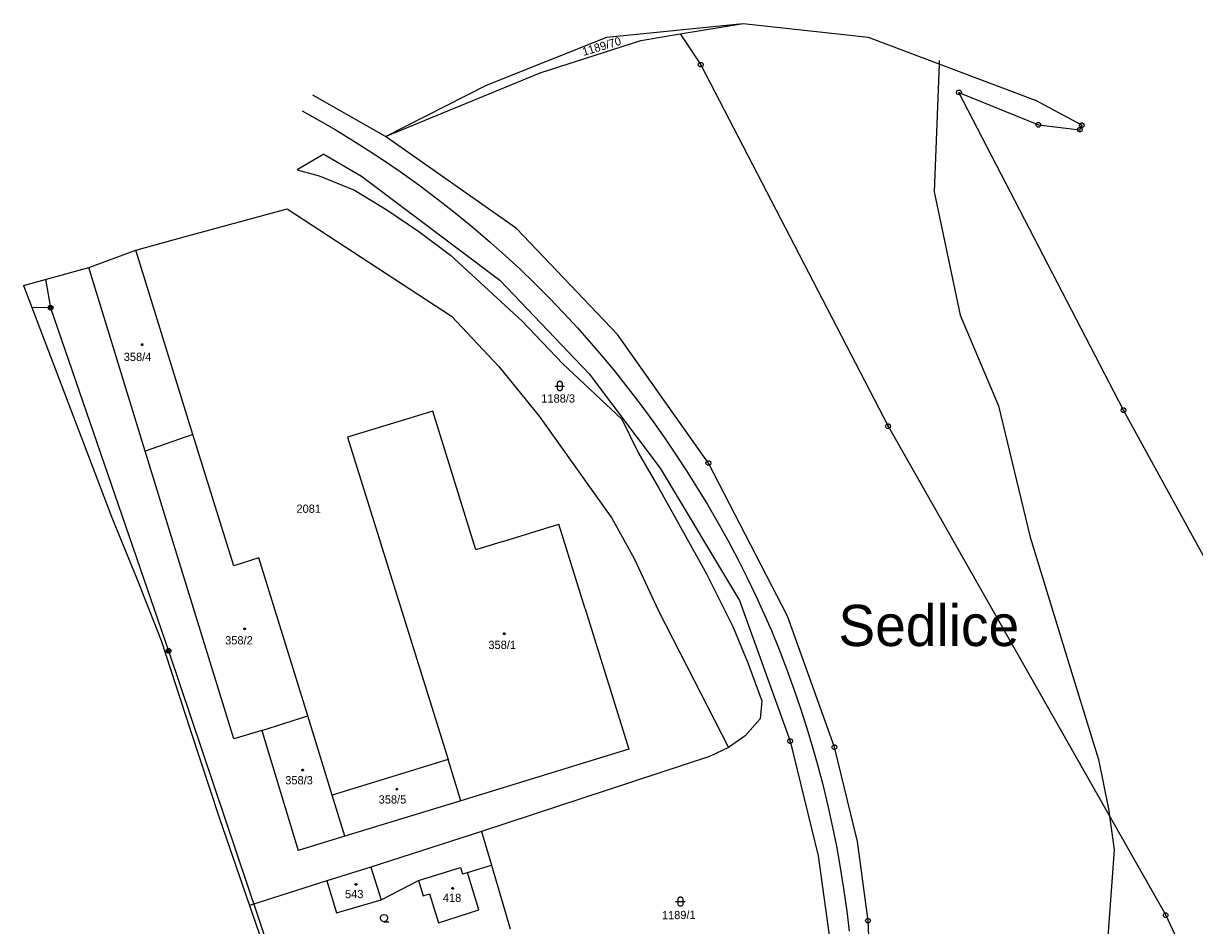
# Model space of a CAD drawing. Extents: x -789470 to -786707, y -1118640 to -1114455.
# Drawn here: x -787871.3 to -787629.8, y -1116508.7 to -1116322.8 of the extents above; entities that cross this region are included whole.
import ezdxf

# ---------------------------------------------------------------- set-up
doc = ezdxf.new("R2010")
doc.units = 0
for name, color, linetype in [('1', 7, 'Continuous'), ('11', 7, 'Continuous'), ('12', 7, 'Continuous'), ('2', 7, 'Continuous'), ('3', 7, 'Continuous'), ('4', 7, 'Continuous'), ('5', 7, 'Continuous'), ('6', 7, 'Continuous'), ('7', 7, 'Continuous'), ('8', 7, 'Continuous')]:
    doc.layers.add(name, color=color, linetype=linetype)

msp = doc.modelspace()

# ---------------------------------------------------------------- linework, layer by layer
at = {"layer": '1'}
for p, q in [((-787751, -1116325.62), (-787722.89, -1116322.78)), ((-787735.88, -1116324.94), (-787722.89, -1116322.78)), ((-787722.89, -1116322.78), (-787697.16, -1116325.6)), ((-787775.84, -1116335.51), (-787751, -1116325.62)), ((-787744.01, -1116326.3), (-787735.88, -1116324.94)), ((-787735.88, -1116324.94), (-787731.65, -1116331.28)), ((-787697.16, -1116325.6), (-787662.68, -1116338.61)), ((-787764.77, -1116332.97), (-787744.01, -1116326.3)), ((-787796.66, -1116346.09), (-787764.77, -1116332.97)), ((-787731.65, -1116331.28), (-787693.03, -1116405.8)), ((-787796.66, -1116346.09), (-787811.61, -1116337.55)), ((-787796.66, -1116346.09), (-787775.84, -1116335.51)), ((-787644.49, -1116402.5), (-787678.42, -1116337)), ((-787678.42, -1116337), (-787662.05, -1116343.67)), ((-787653.08, -1116343.75), (-787662.68, -1116338.61)), ((-787662.05, -1116343.67), (-787653.49, -1116344.69)), ((-787653.49, -1116344.69), (-787653.08, -1116343.75)), ((-787769.63, -1116365.02), (-787796.66, -1116346.09)), ((-787809.33, -1116349.7), (-787814.88, -1116352.94)), ((-787809.33, -1116349.7), (-787801.57, -1116354.26)), ((-787814.88, -1116352.94), (-787810.31, -1116354.2)), ((-787810.31, -1116354.2), (-787803.06, -1116357.15)), ((-787801.57, -1116354.26), (-787773.08, -1116375.71)), ((-787803.06, -1116357.15), (-787796.38, -1116361.2)), ((-787838.93, -1116367), (-787816.95, -1116360.96)), ((-787816.95, -1116360.96), (-787783.07, -1116383.09)), ((-787796.38, -1116361.2), (-787789.77, -1116365.68)), ((-787789.77, -1116365.68), (-787783.23, -1116370.57)), ((-787748.85, -1116386.9), (-787769.63, -1116365.02)), ((-787848.15, -1116369.53), (-787838.93, -1116367)), ((-787857.79, -1116373.06), (-787848.15, -1116369.53)), ((-787836.34, -1116407.53), (-787848.15, -1116369.53)), ((-787783.23, -1116370.57), (-787768.48, -1116384.12)), ((-787871.3, -1116376.78), (-787857.79, -1116373.06)), ((-787846.17, -1116410.91), (-787857.79, -1116373.06)), ((-787773.08, -1116375.71), (-787754.69, -1116394.98)), ((-787871.3, -1116376.78), (-787853.08, -1116424.6)), ((-787783.07, -1116383.09), (-787773.29, -1116393.47)), ((-787768.48, -1116384.12), (-787760.07, -1116392.95)), ((-787730.07, -1116413.4), (-787748.85, -1116386.9)), ((-787760.07, -1116392.95), (-787747.91, -1116404.33)), ((-787773.29, -1116393.47), (-787764.99, -1116403.74)), ((-787754.69, -1116394.98), (-787740.05, -1116414.46)), ((-787786.89, -1116402.68), (-787804.46, -1116408.04)), ((-787778, -1116431.3), (-787786.89, -1116402.68)), ((-787607.93, -1116469.17), (-787644.49, -1116402.5)), ((-787764.99, -1116403.74), (-787750.02, -1116424.78)), ((-787747.91, -1116404.33), (-787744.48, -1116411.34)), ((-787836.34, -1116407.53), (-787846.17, -1116410.91)), ((-787829.71, -1116428.88), (-787836.34, -1116407.53)), ((-787693.03, -1116405.8), (-787635.8, -1116506.59)), ((-787804.46, -1116408.04), (-787783.74, -1116474.49)), ((-787839.65, -1116432.16), (-787846.17, -1116410.91)), ((-787744.48, -1116411.34), (-787740.3, -1116418.54)), ((-787740.05, -1116414.46), (-787723.7, -1116441.75)), ((-787713.77, -1116444.97), (-787730.07, -1116413.4)), ((-787740.3, -1116418.54), (-787730.48, -1116436.2)), ((-787853.08, -1116424.6), (-787847.88, -1116437.41)), ((-787772.45, -1116429.58), (-787760.88, -1116425.98)), ((-787755.47, -1116443.43), (-787760.88, -1116425.98)), ((-787750.02, -1116424.78), (-787745.39, -1116433.08)), ((-787827.94, -1116434.57), (-787829.71, -1116428.88)), ((-787772.45, -1116429.58), (-787778, -1116431.3)), ((-787827.95, -1116470.26), (-787839.65, -1116432.16)), ((-787822.78, -1116432.96), (-787827.94, -1116434.57)), ((-787812.66, -1116465.52), (-787822.78, -1116432.96)), ((-787745.39, -1116433.08), (-787740.36, -1116443.85)), ((-787730.48, -1116436.2), (-787725.06, -1116447.09)), ((-787847.88, -1116437.41), (-787842.91, -1116449.97)), ((-787755.47, -1116443.43), (-787746.51, -1116472.35)), ((-787740.36, -1116443.85), (-787725.95, -1116472.01)), ((-787723.7, -1116441.75), (-787713.22, -1116470.7)), ((-787704.1, -1116471.95), (-787713.77, -1116444.97)), ((-787725.06, -1116447.09), (-787721.94, -1116454.54)), ((-787842.91, -1116449.97), (-787836.94, -1116468.33)), ((-787721.94, -1116454.54), (-787719.06, -1116462.43)), ((-787719.06, -1116462.43), (-787719.42, -1116466.14)), ((-787822.15, -1116468.48), (-787812.66, -1116465.52)), ((-787807.65, -1116481.83), (-787812.66, -1116465.52)), ((-787719.42, -1116466.14), (-787722.51, -1116469.58)), ((-787836.94, -1116468.33), (-787830.95, -1116486.46)), ((-787822.15, -1116468.48), (-787827.95, -1116470.26)), ((-787822.15, -1116468.48), (-787814.66, -1116493.27)), ((-787722.51, -1116469.58), (-787725.95, -1116472.01)), ((-787746.51, -1116472.35), (-787781.13, -1116482.98)), ((-787725.95, -1116472.01), (-787729.82, -1116473.87)), ((-787713.22, -1116470.7), (-787707.44, -1116494.38)), ((-787699.35, -1116491.37), (-787704.1, -1116471.95)), ((-787783.74, -1116474.49), (-787807.65, -1116481.83)), ((-787781.13, -1116482.98), (-787783.74, -1116474.49)), ((-787729.82, -1116473.87), (-787776.83, -1116489.36)), ((-787805.05, -1116490.32), (-787807.65, -1116481.83)), ((-787781.13, -1116482.98), (-787805.05, -1116490.32)), ((-787830.95, -1116486.46), (-787824.68, -1116504.6)), ((-787776.83, -1116489.36), (-787799.7, -1116496.65)), ((-787776.83, -1116489.36), (-787774.8, -1116496.28)), ((-787805.05, -1116490.32), (-787814.66, -1116493.27)), ((-787697.17, -1116507.73), (-787699.35, -1116491.37)), ((-787707.44, -1116494.38), (-787704.74, -1116513.73)), ((-787799.7, -1116496.65), (-787808.76, -1116499.53)), ((-787799.7, -1116496.65), (-787797.55, -1116503.4)), ((-787779.76, -1116497.81), (-787774.8, -1116496.28)), ((-787774.8, -1116496.28), (-787770.94, -1116509.39)), ((-787808.76, -1116499.53), (-787824.68, -1116504.6)), ((-787808.76, -1116499.53), (-787806.78, -1116506.12)), ((-787797.55, -1116503.4), (-787789.88, -1116499.46)), ((-787789.88, -1116499.46), (-787788.87, -1116502.58)), ((-787777.4, -1116505.49), (-787779.76, -1116497.81)), ((-787806.78, -1116506.12), (-787797.55, -1116503.4)), ((-787788.87, -1116502.58), (-787787.57, -1116502.18)), ((-787787.57, -1116502.18), (-787785.72, -1116508.13)), ((-787824.68, -1116504.6), (-787819.38, -1116520)), ((-787785.72, -1116508.13), (-787777.4, -1116505.49)), ((-787635.8, -1116506.59), (-787568.9, -1116647.88)), ((-787695.53, -1116543.16), (-787697.17, -1116507.73))]:
    msp.add_line(p, q, dxfattribs=at)
at = {"layer": '11'}
msp.add_lwpolyline([(-787682.47, -1116330.41), (-787682.5, -1116331.13), (-787683.51, -1116357.47), (-787678.19, -1116382.89), (-787670.29, -1116401.57), (-787663.71, -1116428.69), (-787655.44, -1116455.83), (-787649.65, -1116474.49), (-787647.6, -1116484.65), (-787646.4, -1116493.12), (-787648.27, -1116518.48), (-787648.86, -1116540.46), (-787650.19, -1116548.91), (-787652.39, -1116560.73), (-787656.3, -1116574.23), (-787661.06, -1116587.72), (-787663.2, -1116591.08), (-787677.78, -1116616.32), (-787688.91, -1116633.13), (-787692.34, -1116638.18), (-787695.11, -1116645.4), (-787696.22, -1116648.29), (-787697.58, -1116660.12)], dxfattribs=at)
at = {"layer": '12'}
for p, q in [((-787857.79, -1116373.06), (-787848.15, -1116369.53)), ((-787836.34, -1116407.53), (-787848.15, -1116369.53)), ((-787846.17, -1116410.91), (-787857.79, -1116373.06)), ((-787786.89, -1116402.68), (-787804.46, -1116408.04)), ((-787778, -1116431.3), (-787786.89, -1116402.68)), ((-787836.34, -1116407.53), (-787846.17, -1116410.91)), ((-787836.34, -1116407.53), (-787846.17, -1116410.91)), ((-787829.71, -1116428.88), (-787836.34, -1116407.53)), ((-787804.46, -1116408.04), (-787783.74, -1116474.49)), ((-787839.65, -1116432.16), (-787846.17, -1116410.91)), ((-787772.45, -1116429.58), (-787760.88, -1116425.98)), ((-787755.47, -1116443.43), (-787760.88, -1116425.98)), ((-787827.94, -1116434.57), (-787829.71, -1116428.88)), ((-787772.45, -1116429.58), (-787778, -1116431.3)), ((-787827.95, -1116470.26), (-787839.65, -1116432.16)), ((-787822.78, -1116432.96), (-787827.94, -1116434.57)), ((-787812.66, -1116465.52), (-787822.78, -1116432.96)), ((-787755.47, -1116443.43), (-787746.51, -1116472.35)), ((-787822.15, -1116468.48), (-787812.66, -1116465.52)), ((-787822.15, -1116468.48), (-787812.66, -1116465.52)), ((-787807.65, -1116481.83), (-787812.66, -1116465.52)), ((-787822.15, -1116468.48), (-787827.95, -1116470.26)), ((-787822.15, -1116468.48), (-787814.66, -1116493.27)), ((-787746.51, -1116472.35), (-787781.13, -1116482.98)), ((-787783.74, -1116474.49), (-787807.65, -1116481.83)), ((-787781.13, -1116482.98), (-787783.74, -1116474.49)), ((-787781.13, -1116482.98), (-787783.74, -1116474.49)), ((-787805.05, -1116490.32), (-787807.65, -1116481.83)), ((-787805.05, -1116490.32), (-787807.65, -1116481.83)), ((-787781.13, -1116482.98), (-787805.05, -1116490.32)), ((-787805.05, -1116490.32), (-787814.66, -1116493.27)), ((-787799.7, -1116496.65), (-787808.76, -1116499.53)), ((-787799.7, -1116496.65), (-787797.55, -1116503.4)), ((-787789.88, -1116499.46), (-787781.17, -1116496.76)), ((-787781.17, -1116496.76), (-787780.77, -1116498.06)), ((-787808.76, -1116499.53), (-787806.78, -1116506.12)), ((-787789.88, -1116499.46), (-787788.87, -1116502.58)), ((-787780.77, -1116498.06), (-787779.76, -1116497.81)), ((-787777.4, -1116505.49), (-787779.76, -1116497.81)), ((-787806.78, -1116506.12), (-787797.55, -1116503.4)), ((-787788.87, -1116502.58), (-787787.57, -1116502.18)), ((-787787.57, -1116502.18), (-787785.72, -1116508.13)), ((-787785.72, -1116508.13), (-787777.4, -1116505.49))]:
    msp.add_line(p, q, dxfattribs=at)
at = {"layer": '3'}
for points in [[(-787761.72, -1116397.51), (-787760.45, -1116397.51), (-787759.72, -1116397.51)], [(-787736.84, -1116503.78), (-787735.57, -1116503.78), (-787734.84, -1116503.78)], [(-787796.95, -1116507.92), (-787797.33, -1116507.82), (-787797.6, -1116507.55), (-787797.7, -1116507.18), (-787797.6, -1116506.81), (-787797.33, -1116506.54), (-787796.96, -1116506.44), (-787796.59, -1116506.54), (-787796.32, -1116506.81), (-787796.22, -1116507.19), (-787796.32, -1116507.57), (-787796.59, -1116507.84), (-787796.97, -1116507.94), (-787795.97, -1116507.94)]]:
    msp.add_lwpolyline(points, dxfattribs=at)
for points in [[(-787761.22, -1116397.01), (-787761.12, -1116396.72), (-787760.87, -1116396.54), (-787760.56, -1116396.54), (-787760.31, -1116396.72), (-787760.21, -1116397.01), (-787760.21, -1116398.01), (-787760.31, -1116398.3), (-787760.56, -1116398.48), (-787760.87, -1116398.48), (-787761.12, -1116398.3), (-787761.22, -1116398.01)], [(-787736.34, -1116503.28), (-787736.24, -1116502.99), (-787735.99, -1116502.81), (-787735.68, -1116502.81), (-787735.43, -1116502.99), (-787735.33, -1116503.28), (-787735.33, -1116504.28), (-787735.43, -1116504.57), (-787735.68, -1116504.75), (-787735.99, -1116504.75), (-787736.24, -1116504.57), (-787736.34, -1116504.28)]]:
    msp.add_lwpolyline(points, close=True, dxfattribs=at)
at = {"layer": '4'}
for p, q in [((-787789.88, -1116499.46), (-787781.17, -1116496.76)), ((-787781.17, -1116496.76), (-787780.77, -1116498.06)), ((-787780.77, -1116498.06), (-787779.76, -1116497.81))]:
    msp.add_line(p, q, dxfattribs=at)
at = {"layer": '5'}
for points in [[(-787846.8, -1116388.83), (-787846.7, -1116388.85), (-787846.65, -1116388.94), (-787846.63, -1116389), (-787846.65, -1116389.09), (-787846.73, -1116389.16), (-787846.8, -1116389.17), (-787846.89, -1116389.14), (-787846.95, -1116389.08), (-787846.97, -1116389), (-787846.95, -1116388.91), (-787846.87, -1116388.84)], [(-787825.69, -1116447.4), (-787825.59, -1116447.42), (-787825.54, -1116447.51), (-787825.52, -1116447.57), (-787825.54, -1116447.66), (-787825.62, -1116447.73), (-787825.69, -1116447.74), (-787825.78, -1116447.71), (-787825.84, -1116447.65), (-787825.86, -1116447.57), (-787825.84, -1116447.48), (-787825.76, -1116447.41)], [(-787772.15, -1116448.4), (-787772.05, -1116448.42), (-787772, -1116448.51), (-787771.98, -1116448.57), (-787772, -1116448.66), (-787772.08, -1116448.73), (-787772.15, -1116448.74), (-787772.24, -1116448.71), (-787772.3, -1116448.65), (-787772.32, -1116448.57), (-787772.3, -1116448.48), (-787772.22, -1116448.41)], [(-787813.72, -1116476.5), (-787813.62, -1116476.52), (-787813.57, -1116476.61), (-787813.55, -1116476.67), (-787813.57, -1116476.76), (-787813.65, -1116476.83), (-787813.72, -1116476.84), (-787813.81, -1116476.81), (-787813.87, -1116476.75), (-787813.89, -1116476.67), (-787813.87, -1116476.58), (-787813.79, -1116476.51)], [(-787794.33, -1116480.44), (-787794.23, -1116480.46), (-787794.18, -1116480.55), (-787794.16, -1116480.61), (-787794.18, -1116480.7), (-787794.26, -1116480.77), (-787794.33, -1116480.78), (-787794.42, -1116480.75), (-787794.48, -1116480.69), (-787794.5, -1116480.61), (-787794.48, -1116480.52), (-787794.4, -1116480.45)], [(-787802.72, -1116500.06), (-787802.62, -1116500.08), (-787802.57, -1116500.17), (-787802.55, -1116500.23), (-787802.57, -1116500.32), (-787802.65, -1116500.39), (-787802.72, -1116500.4), (-787802.81, -1116500.37), (-787802.87, -1116500.31), (-787802.89, -1116500.23), (-787802.87, -1116500.14), (-787802.79, -1116500.07)], [(-787782.8, -1116500.87), (-787782.7, -1116500.89), (-787782.65, -1116500.98), (-787782.63, -1116501.04), (-787782.65, -1116501.13), (-787782.73, -1116501.2), (-787782.8, -1116501.21), (-787782.89, -1116501.18), (-787782.95, -1116501.12), (-787782.97, -1116501.04), (-787782.95, -1116500.95), (-787782.87, -1116500.88)]]:
    msp.add_lwpolyline(points, close=True, dxfattribs=at)
at = {"layer": '6'}
for p, q in [((-787866.72, -1116375.52), (-787865.71, -1116381.37)), ((-787865.71, -1116381.37), (-787869.58, -1116381.31)), ((-787865.71, -1116381.37), (-787841.37, -1116452.11)), ((-787841.37, -1116452.11), (-787814.56, -1116531.75))]:
    msp.add_line(p, q, dxfattribs=at)
for points in [[(-787813.81, -1116340.77), (-787810.52, -1116342.62), (-787807.04, -1116344.65), (-787803.61, -1116346.75), (-787800.21, -1116348.91), (-787797.06, -1116350.99), (-787793.65, -1116353.32), (-787789.79, -1116356.08), (-787785.99, -1116358.93), (-787782.26, -1116361.85), (-787778.59, -1116364.85), (-787774.98, -1116367.93), (-787771.89, -1116370.68)], [(-787771.89, -1116370.68), (-787769.03, -1116373.32), (-787765.95, -1116376.29), (-787762.93, -1116379.31), (-787759.96, -1116382.4), (-787757.06, -1116385.54), (-787754.22, -1116388.74), (-787751.69, -1116391.7), (-787749.22, -1116394.68), (-787746.59, -1116398), (-787744.02, -1116401.36), (-787741.51, -1116404.78), (-787739.07, -1116408.24), (-787736.7, -1116411.75), (-787734.6, -1116415)], [(-787865.86, -1116380.89), (-787865.55, -1116380.89), (-787865.3, -1116381.07), (-787865.2, -1116381.36), (-787865.3, -1116381.65), (-787865.55, -1116381.83), (-787865.86, -1116381.83), (-787866.11, -1116381.65), (-787866.21, -1116381.36), (-787866.11, -1116381.07), (-787865.86, -1116380.89), (-787865.83, -1116380.93), (-787865.59, -1116380.93), (-787865.43, -1116381.01), (-787865.99, -1116381.01), (-787866.07, -1116381.09), (-787865.35, -1116381.09), (-787865.35, -1116381.17), (-787866.07, -1116381.17), (-787866.11, -1116381.25), (-787865.31, -1116381.25), (-787865.27, -1116381.33), (-787866.15, -1116381.33), (-787866.15, -1116381.41), (-787865.27, -1116381.41), (-787865.3, -1116381.49), (-787866.11, -1116381.49), (-787866.1, -1116381.57), (-787865.29, -1116381.57), (-787865.34, -1116381.65), (-787866.06, -1116381.65), (-787865.98, -1116381.73), (-787865.42, -1116381.73), (-787865.53, -1116381.81), (-787865.87, -1116381.81)], [(-787734.6, -1116415), (-787732.52, -1116418.26), (-787730.27, -1116421.92), (-787728.11, -1116425.63), (-787726.02, -1116429.39), (-787724.01, -1116433.19), (-787722.07, -1116437.02), (-787720.22, -1116440.9), (-787718.62, -1116444.42), (-787717.09, -1116447.93), (-787715.48, -1116451.85), (-787713.96, -1116455.79), (-787712.51, -1116459.77), (-787711.14, -1116463.77), (-787709.85, -1116467.8), (-787708.76, -1116471.47)], [(-787841.52, -1116451.63), (-787841.21, -1116451.63), (-787840.96, -1116451.81), (-787840.86, -1116452.1), (-787840.96, -1116452.39), (-787841.21, -1116452.57), (-787841.52, -1116452.57), (-787841.77, -1116452.39), (-787841.87, -1116452.1), (-787841.77, -1116451.81), (-787841.52, -1116451.63), (-787841.49, -1116451.67), (-787841.25, -1116451.67), (-787841.09, -1116451.75), (-787841.65, -1116451.75), (-787841.73, -1116451.83), (-787841.01, -1116451.83), (-787841.01, -1116451.91), (-787841.73, -1116451.91), (-787841.77, -1116451.99), (-787840.97, -1116451.99), (-787840.93, -1116452.07), (-787841.81, -1116452.07), (-787841.81, -1116452.15), (-787840.93, -1116452.15), (-787840.96, -1116452.23), (-787841.77, -1116452.23), (-787841.76, -1116452.31), (-787840.95, -1116452.31), (-787841, -1116452.39), (-787841.72, -1116452.39), (-787841.64, -1116452.47), (-787841.08, -1116452.47), (-787841.19, -1116452.55), (-787841.53, -1116452.55)], [(-787708.76, -1116471.47), (-787707.66, -1116475.3), (-787706.5, -1116479.65), (-787705.44, -1116484.02), (-787704.47, -1116488.41), (-787703.69, -1116492.32), (-787702.95, -1116496.37), (-787702.2, -1116501.07), (-787701.55, -1116505.78), (-787701.08, -1116509.87)]]:
    msp.add_lwpolyline(points, dxfattribs=at)
at = {"layer": '8'}
for p, q in [((-787731.77, -1116331.28), (-787731.53, -1116331.28)), ((-787678.54, -1116337), (-787678.3, -1116337)), ((-787662.17, -1116343.67), (-787661.93, -1116343.67)), ((-787653.61, -1116344.69), (-787653.37, -1116344.69)), ((-787653.2, -1116343.75), (-787652.96, -1116343.75)), ((-787644.61, -1116402.5), (-787644.37, -1116402.5)), ((-787693.15, -1116405.8), (-787692.91, -1116405.8)), ((-787730.19, -1116413.4), (-787729.95, -1116413.4)), ((-787713.34, -1116470.7), (-787713.1, -1116470.7)), ((-787704.22, -1116471.95), (-787703.98, -1116471.95)), ((-787635.92, -1116506.59), (-787635.68, -1116506.59)), ((-787697.29, -1116507.73), (-787697.05, -1116507.73))]:
    msp.add_line(p, q, dxfattribs=at)
for points in [[(-787731.5, -1116330.8), (-787731.25, -1116330.98), (-787731.15, -1116331.27), (-787731.25, -1116331.56), (-787731.5, -1116331.74), (-787731.81, -1116331.74), (-787732.06, -1116331.56), (-787732.16, -1116331.27), (-787732.06, -1116330.98), (-787731.81, -1116330.8)], [(-787678.27, -1116336.52), (-787678.02, -1116336.7), (-787677.92, -1116336.99), (-787678.02, -1116337.28), (-787678.27, -1116337.46), (-787678.58, -1116337.46), (-787678.83, -1116337.28), (-787678.93, -1116336.99), (-787678.83, -1116336.7), (-787678.58, -1116336.52)], [(-787661.9, -1116343.19), (-787661.65, -1116343.37), (-787661.55, -1116343.66), (-787661.65, -1116343.95), (-787661.9, -1116344.13), (-787662.21, -1116344.13), (-787662.46, -1116343.95), (-787662.56, -1116343.66), (-787662.46, -1116343.37), (-787662.21, -1116343.19)], [(-787653.34, -1116344.21), (-787653.09, -1116344.39), (-787652.99, -1116344.68), (-787653.09, -1116344.97), (-787653.34, -1116345.15), (-787653.65, -1116345.15), (-787653.9, -1116344.97), (-787654, -1116344.68), (-787653.9, -1116344.39), (-787653.65, -1116344.21)], [(-787652.93, -1116343.27), (-787652.68, -1116343.45), (-787652.58, -1116343.74), (-787652.68, -1116344.03), (-787652.93, -1116344.21), (-787653.24, -1116344.21), (-787653.49, -1116344.03), (-787653.59, -1116343.74), (-787653.49, -1116343.45), (-787653.24, -1116343.27)], [(-787644.34, -1116402.02), (-787644.09, -1116402.2), (-787643.99, -1116402.49), (-787644.09, -1116402.78), (-787644.34, -1116402.96), (-787644.65, -1116402.96), (-787644.9, -1116402.78), (-787645, -1116402.49), (-787644.9, -1116402.2), (-787644.65, -1116402.02)], [(-787692.88, -1116405.32), (-787692.63, -1116405.5), (-787692.53, -1116405.79), (-787692.63, -1116406.08), (-787692.88, -1116406.26), (-787693.19, -1116406.26), (-787693.44, -1116406.08), (-787693.54, -1116405.79), (-787693.44, -1116405.5), (-787693.19, -1116405.32)], [(-787729.92, -1116412.92), (-787729.67, -1116413.1), (-787729.57, -1116413.39), (-787729.67, -1116413.68), (-787729.92, -1116413.86), (-787730.23, -1116413.86), (-787730.48, -1116413.68), (-787730.58, -1116413.39), (-787730.48, -1116413.1), (-787730.23, -1116412.92)], [(-787713.07, -1116470.22), (-787712.82, -1116470.4), (-787712.72, -1116470.69), (-787712.82, -1116470.98), (-787713.07, -1116471.16), (-787713.38, -1116471.16), (-787713.63, -1116470.98), (-787713.73, -1116470.69), (-787713.63, -1116470.4), (-787713.38, -1116470.22)], [(-787703.95, -1116471.47), (-787703.7, -1116471.65), (-787703.6, -1116471.94), (-787703.7, -1116472.23), (-787703.95, -1116472.41), (-787704.26, -1116472.41), (-787704.51, -1116472.23), (-787704.61, -1116471.94), (-787704.51, -1116471.65), (-787704.26, -1116471.47)], [(-787635.65, -1116506.11), (-787635.4, -1116506.29), (-787635.3, -1116506.58), (-787635.4, -1116506.87), (-787635.65, -1116507.05), (-787635.96, -1116507.05), (-787636.21, -1116506.87), (-787636.31, -1116506.58), (-787636.21, -1116506.29), (-787635.96, -1116506.11)], [(-787697.02, -1116507.25), (-787696.77, -1116507.43), (-787696.67, -1116507.72), (-787696.77, -1116508.01), (-787697.02, -1116508.19), (-787697.33, -1116508.19), (-787697.58, -1116508.01), (-787697.68, -1116507.72), (-787697.58, -1116507.43), (-787697.33, -1116507.25)]]:
    msp.add_lwpolyline(points, close=True, dxfattribs=at)

# ---------------------------------------------------------------- texts
at = {"layer": '2'}
for s, rotation, p in [('1189/70', 16.6731, (-787755.79, -1116329.48)), ('1189/1', 0.8021, (-787739.65, -1116507.44))]:
    msp.add_text(s, height=1.7, rotation=rotation, dxfattribs=at).set_placement(p)
for s, p in [('358/4', (-787850.61, -1116392.35)), ('1188/3', (-787764.53, -1116400.93)), ('2081', (-787815.01, -1116423.65)), ('358/2', (-787829.71, -1116450.77)), ('358/1', (-787775.43, -1116451.72)), ('358/3', (-787817.32, -1116479.62)), ('358/5', (-787798.06, -1116483.57)), ('543', (-787805, -1116503.07)), ('418', (-787784.82, -1116503.84))]:
    msp.add_text(s, height=1.7, dxfattribs=at).set_placement(p)
at = {"layer": '7'}
msp.add_text('Sedlice', height=8.5, dxfattribs=at).set_placement((-787703.28, -1116451.11))

doc.saveas('drawing.dxf')
